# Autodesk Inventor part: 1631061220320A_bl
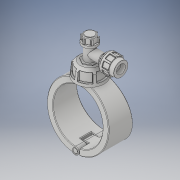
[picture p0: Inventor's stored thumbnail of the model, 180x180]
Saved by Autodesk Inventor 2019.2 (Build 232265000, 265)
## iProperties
Created: 2022-02
Part Number: 1631061220320A_bl
Material: Generic
Description: Plassadle Tapper 177x32
Document SubType Name: Modeling
Designer: comp2
Density: 1 g/cm^3
Appearance: Default
Author: comp2
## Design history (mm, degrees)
derived "16310.ipt"
feature "Solid1::16310.ipt" dims "ScaleForDerivedMember" = 10
feature "Solid2::16310.ipt" dims "ScaleForDerivedMember" = 10
feature "Solid3::16310.ipt" dims "ScaleForDerivedMember" = 10
feature "Solid4::16310.ipt" dims "ScaleForDerivedMember" = 10
tag "TaggingFeature1"
body "Solid1"
body "Solid2"
body "Solid3"
body "Solid4"
other parameters: "d0" = 177 [user parameter], "d3" = 88.5 [user parameter], "d7" = 209 [user parameter], "d8" = 85 deg [user parameter], "d9" = 45 deg [user parameter], "d10" = 102 [user parameter], "d11" = 52 [user parameter], "d12" = 36.4 [user parameter], "d13" = 35.7 [user parameter], "d14" = 55.08 [user parameter], "d15" = 2.6 [user parameter], "d16" = 2 [user parameter], "d17" = 2 [user parameter], "d18" = 31.2 [user parameter], "d19" = 7.8 [user parameter], "d20" = 1 [user parameter], "d21" = 30.6 [user parameter], "d22" = 1 [user parameter], "d23" = 15.6 [user parameter], "d24" = 111 [user parameter], "d27" = 144 [user parameter], "d29" = 64 [user parameter], "d31" = 51.2 [user parameter], "d32" = 44.4 [user parameter], "d33" = 15.54 [user parameter], "d34" = 93 deg [user parameter], "d35" = 2 [user parameter], "d36" = 4 [user parameter], "d39" = 45 deg [user parameter], "d40" = 4 [user parameter], "d41" = 5 [user parameter], "d42" = 4.3 [user parameter], "d46" = 51 [user parameter], "d47" = 32 [user parameter], "d48" = 52 [user parameter], "d49" = 4.4 [user parameter], "d51" = 0 [user parameter], "d52" = 30.1 [user parameter], "d53" = 121 [user parameter], "d54" = 38.5 [user parameter], "d55" = 0 [user parameter], "d56" = 22 [user parameter], "d57" = 22 [user parameter], "d59" = 0 [user parameter], "d61" = 0 [user parameter], "d62" = 38.5 [user parameter], "d63" = 0 [user parameter], "d65" = 0 [user parameter], "d67" = 0 [user parameter], "d69" = 0 [user parameter], "d70" = 1 [user parameter], "d71" = 105.6 [user parameter], "d72" = 0 [user parameter], "d73" = 2 [user parameter], "d77" = 32 [user parameter], "d78" = 86.7 [user parameter], "d79" = 5.1 [user parameter], "d80" = 60 deg [user parameter], "d81" = 5.1 [user parameter], "d84" = 0 [user parameter], "d85" = 1 [user parameter], "d87" = 360 deg [user parameter], "d90" = 0 [user parameter], "d91" = 1 [user parameter], "d93" = 60 deg [user parameter], "d94" = 3.06 [user parameter], "d95" = 3.06 [user parameter], "d97" = 0 [user parameter], "d98" = 0.5 [user parameter], "d100" = 360 deg [user parameter], "d102" = 2 [user parameter], "d105" = 0 [user parameter], "d106" = 45 deg [user parameter], "d107" = 3.2 [user parameter], "d108" = 3.2 [user parameter], "d109" = 2.95332 [user parameter], "d110" = -8 [user parameter], "d112" = 0 [user parameter], "d113" = 0.5 [user parameter], "d115" = 360 deg [user parameter], "d117" = 0.5 [user parameter], "d" = 177 [user parameter], "d1" = 32 [user parameter], "E_" = 64 [user parameter], "E1" = 102 [user parameter], "H2" = 144 [user parameter], "H3" = 111 [user parameter], "H_costum" = 52 [user parameter]
